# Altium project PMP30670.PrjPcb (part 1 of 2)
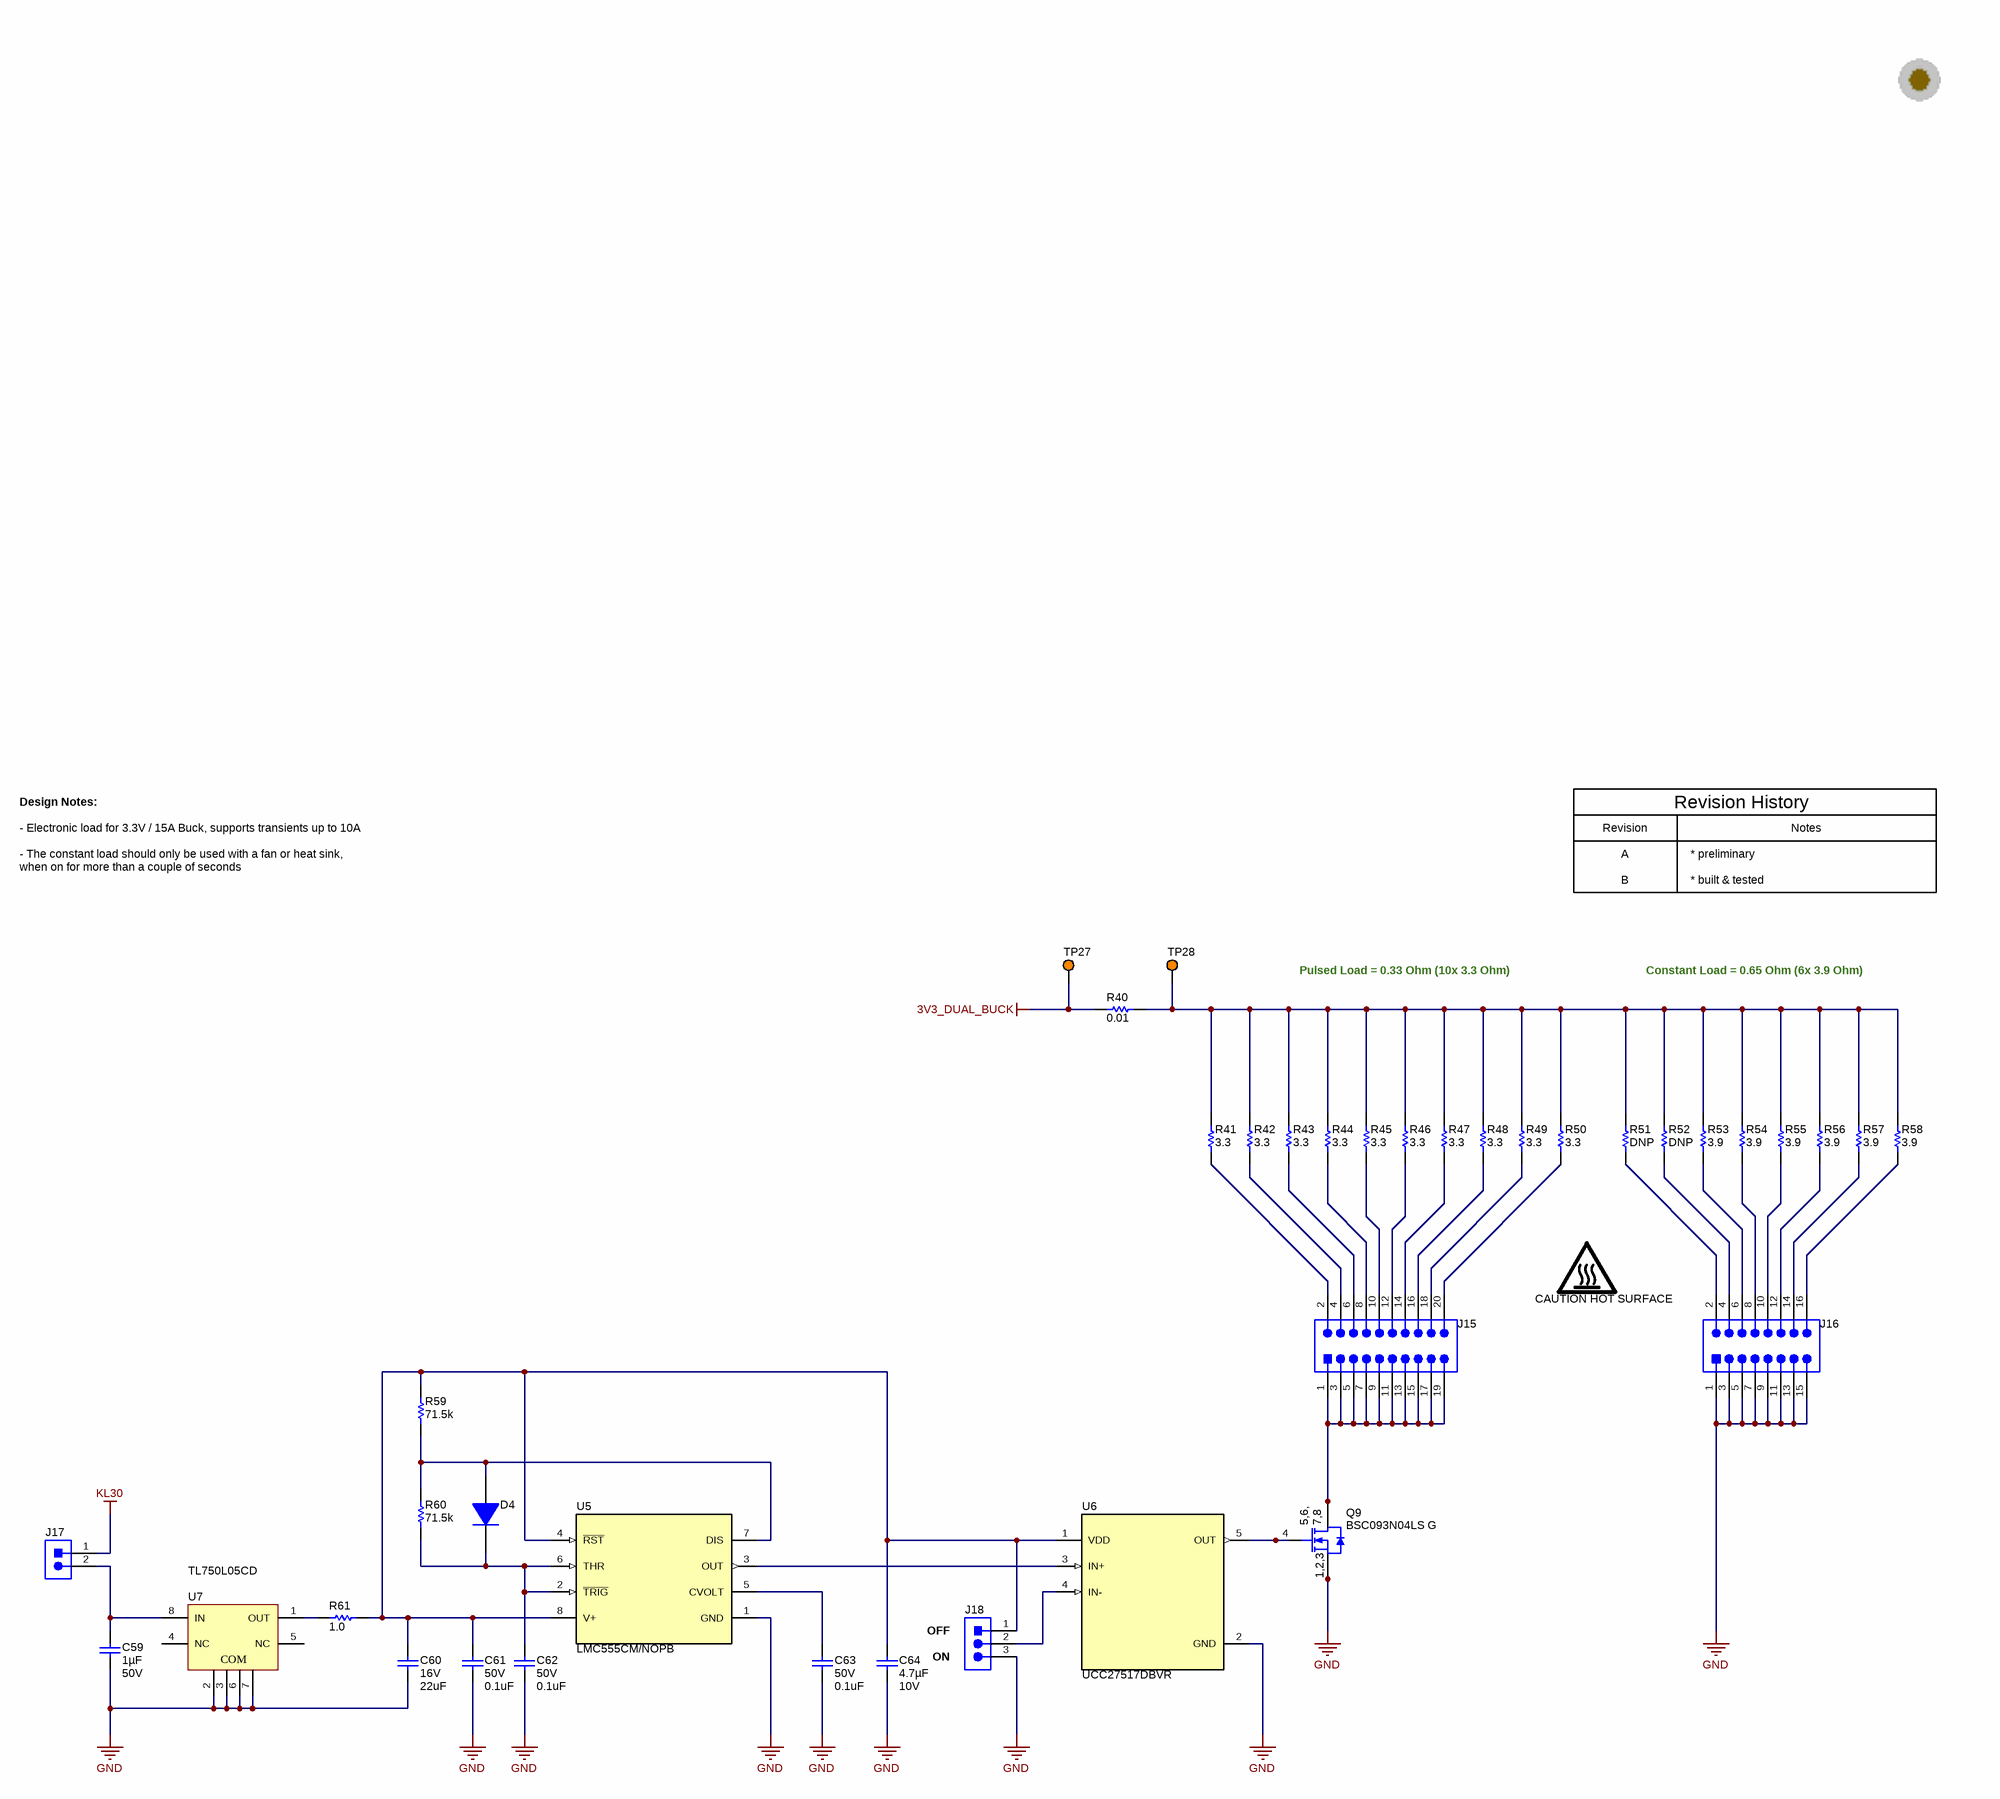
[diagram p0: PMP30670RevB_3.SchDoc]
TID: N/A; TechSupport: http://www.ti.com/support; SCH_Rev: B; PRJ_Title: Automotive Frontend Power Supply; PRJ_Number: PMP30670; PRJ_Engineer: M Zehendner; PRJ_Customer: Public Release; PCB_Rev: A; CopyrightYear: 2019
3 sheets, 200 parts. Net scope: global (net labels, ports and power ports of the same name join across sheets).
Board file: PMP30670.PcbDoc
Sheets:
  PMP30670RevB_3.SchDoc
  PMP30670RevB_2.SchDoc
  PMP30670RevB_1.SchDoc

## Sheet PMP30670RevB_3.SchDoc: PMP30670RevA_3
size A3; Date: Not shown in title block; ApprovedBy: Not shown in title block; CheckedBy: Not shown in title block; Author: Not shown in title block; CompanyName: Not shown in title block; DrawnBy: M Zehendner; Engineer: Not shown in title block; Organization: Not shown in title block; Address1: Not shown in title block; Address2: Not shown in title block; Address3: Not shown in title block; Address4: Not shown in title block; DocumentNumber: 3; Revision: Use project parameter SCH_Rev; SheetNumber: 3; SheetTotal: 3; PageSetup: Record=PageOptions¦CenterHorizontal=True¦CenterVertical=True¦PrintScale=0.70¦XCorrection=1.00¦YCorrection=1.00¦PrintKind=0¦BorderSize=5000000¦LeftOffset=0¦BottomOffset=0¦Orientation=2¦PaperLength=1000¦PaperWidth=1000¦Scale=100¦PaperSource=15¦PrintQuality=600¦MediaType=1¦DitherType=10¦PaperKind=A4¦PrintScaleMode=1

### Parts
C59  Cap_F: 1µF  VDC_V: 50V  [0805_HV]  (hidden comment: GRM21BR71H105KA12L)
C60  VDC_V: 16V  ValueDisplayed: 22uF  [1210_270]  (hidden comment: GRM32ER71C226ME18L)
C61  VDC_V: 50V  ValueDisplayed: 0.1uF  [0402]  (hidden comment: GRM155R71H104ME14D)
C62  VDC_V: 50V  ValueDisplayed: 0.1uF  [0402]  (hidden comment: GRM155R71H104ME14D)
C63  VDC_V: 50V  ValueDisplayed: 0.1uF  [0402]  (hidden comment: GRM155R71H104ME14D)
C64  Cap_F: 4.7µF  VDC_V: 10V  [0805_HV]  (hidden comment: GRM21BR71A475KA73L)
CAUTION!_HOT_SURFACE!1  CAUTION HOT SURFACE  [IEC_HotSurface_Large]  (no BOM)
D4  1N4148WFL-G3-08  [SOD-123FL]  (value not drawn)
J15  TSW-110-07-G-D  [TSW-110-07-G-D]  (value not drawn)
J16  TSW-108-07-G-D  [TSW-108-07-G-D]  (value not drawn)
J17  TSW-102-07-G-S  [TSW-102-07-G-S]  (value not drawn)
J18  TSW-103-07-G-S  [TSW-103-07-G-S]  (value not drawn)
Q9  BSC093N04LS G  [PG-TDSON-8]
R40  ValueDisplayed: 0.01  [PWR4412-2S-3W]  (hidden comment: OAR3R010FLF)
R41  ValueDisplayed: 3.3  [2512]  (hidden comment: CRCW25123R30JNEG)
R42  ValueDisplayed: 3.3  [2512]  (hidden comment: CRCW25123R30JNEG)
R43  ValueDisplayed: 3.3  [2512]  (hidden comment: CRCW25123R30JNEG)
R44  ValueDisplayed: 3.3  [2512]  (hidden comment: CRCW25123R30JNEG)
R45  ValueDisplayed: 3.3  [2512]  (hidden comment: CRCW25123R30JNEG)
R46  ValueDisplayed: 3.3  [2512]  (hidden comment: CRCW25123R30JNEG)
R47  ValueDisplayed: 3.3  [2512]  (hidden comment: CRCW25123R30JNEG)
R48  ValueDisplayed: 3.3  [2512]  (hidden comment: CRCW25123R30JNEG)
R49  ValueDisplayed: 3.3  [2512]  (hidden comment: CRCW25123R30JNEG)
R50  ValueDisplayed: 3.3  [2512]  (hidden comment: CRCW25123R30JNEG)
R51  ValueDisplayed: DNP  [2512]  (hidden comment: CRCW251212R1FKEG)
R52  ValueDisplayed: DNP  [2512]  (hidden comment: CRCW251212R1FKEG)
R53  ValueDisplayed: 3.9  [2512]  (hidden comment: CRCW25123R90JNEG)
R54  ValueDisplayed: 3.9  [2512]  (hidden comment: CRCW25123R90JNEG)
R55  ValueDisplayed: 3.9  [2512]  (hidden comment: CRCW25123R90JNEG)
R56  ValueDisplayed: 3.9  [2512]  (hidden comment: CRCW25123R90JNEG)
R57  ValueDisplayed: 3.9  [2512]  (hidden comment: CRCW25123R90JNEG)
R58  ValueDisplayed: 3.9  [2512]  (hidden comment: CRCW25123R90JNEG)
R59  ValueDisplayed: 71.5k  [0603]  (hidden comment: CRCW060371K5FKEA)
R60  ValueDisplayed: 71.5k  [0603]  (hidden comment: CRCW060371K5FKEA)
R61  ValueDisplayed: 1.0  [0603]  (hidden comment: CRCW06031R00JNEA)
TP27  5013  [Keystone5013]  (value not drawn)
TP28  5013  [Keystone5013]  (value not drawn)
U5  LMC555CM/NOPB  [D0008A_N]
U6  UCC27517DBVR  [DBV0005A_N]
U7  TL750L05CD  [D0008A_N]

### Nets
3V3_DUAL_BUCK: R40.1 TP27.1
GND: C59.2 C60.2 C61.2 C62.2 C63.2 C64.2 J16.1 J16.3 J16.5 J16.7 J16.9 J16.11 J16.13 J16.15 J18.3 Q9.1(S) Q9.2(S) Q9.3(S) U5.1(GND) U6.2(GND) U7.2(COM) U7.3(COM) U7.6(COM) U7.7(COM)
KL30: J17.1
NetC59_1: C59.1 J17.2 U7.8(IN)
NetC60_1: C60.1 C61.1 C64.1 J18.1 R59.2 R61.2 U5.4(~{RST}) U5.8(V+) U6.1(VDD)
NetC62_1: C62.1 D4.1(K) R60.1 U5.2(~{TRIG}) U5.6(THR)
NetC63_1: C63.1 U5.5(CVOLT)
NetD4_2: D4.2(A) R59.1 R60.2 U5.7(DIS)
NetJ15_1: J15.1 J15.3 J15.5 J15.7 J15.9 J15.11 J15.13 J15.15 J15.17 J15.19 Q9.5(D) Q9.6(D) Q9.7(D) Q9.8(D) Q9.9(D)
NetJ15_2: J15.2 R41.1
NetJ15_4: J15.4 R42.1
NetJ15_6: J15.6 R43.1
NetJ15_8: J15.8 R44.1
NetJ15_10: J15.10 R45.1
NetJ15_12: J15.12 R46.1
NetJ15_14: J15.14 R47.1
NetJ15_16: J15.16 R48.1
NetJ15_18: J15.18 R49.1
NetJ15_20: J15.20 R50.1
NetJ16_2: J16.2 R51.1
NetJ16_4: J16.4 R52.1
NetJ16_6: J16.6 R53.1
NetJ16_8: J16.8 R54.1
NetJ16_10: J16.10 R55.1
NetJ16_12: J16.12 R56.1
NetJ16_14: J16.14 R57.1
NetJ16_16: J16.16 R58.1
NetJ18_2: J18.2 U6.4(IN-)
NetQ9_4: Q9.4(G) U6.5(OUT)
NetR40_2: R40.2 R41.2 R42.2 R43.2 R44.2 R45.2 R46.2 R47.2 R48.2 R49.2 R50.2 R51.2 R52.2 R53.2 R54.2 R55.2 R56.2 R57.2 R58.2 TP28.1
NetR61_1: R61.1 U7.1(OUT)
NetU5_3: U5.3(OUT) U6.3(IN+)

Not connected (* = marked no-connect by the designer): U7 4(NC) 5(NC)

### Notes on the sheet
- Design Notes:
- - Electronic load for 3.3V / 15A Buck, supports transients up to 10A
- - The constant load should only be used with a fan or heat sink,
- Revision
- A
- * preliminary
- Revision History
- Notes
- when on for more than a couple of seconds
- B
- * built & tested
- Pulsed Load = 0.33 Ohm (10x 3.3 Ohm)
- Constant Load = 0.65 Ohm (6x 3.9 Ohm)
- OFF
- ON

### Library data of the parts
C59 = CMP-0008350-2: CAP, CERM, 1 uF, 50 V, +/- 10%, X7R, 0805; Manufacturer: MuRata; TaMin_C: -55°C; Polarized: N; SizeAreaWB_mm2: 6.75; Value1: Unknown; U/M: EA; Value: 1uF; TaMax_C: 125°C; SizeZ_mm: 1.45; SizeX_mm: 2; SizeY_mm: 1.25; Cap_Case: 0805; SizeArea_mm2: 2.5; AEC Category: Q200
C60 = CMP-0009223-2: CAP, CERM, 22 uF, 16 V, +/- 20%, X7R, 1210; Manufacturer: MuRata; TaMin_C: -55°C; ESR_ohm: 3m; Polarized: N; SizeAreaWB_mm2: 14.7; Value1: 0.003 ohm; U/M: EA; Value: 22uF; TaMax_C: 125°C; SizeZ_mm: 2.7; SizeX_mm: 3.2; SizeY_mm: 2.5; Cap_Case: 1210; SizeArea_mm2: 8; Cap_F: 22µF; IRMS_A: 3.2A; AEC Category: Q200
C61-C63 = CMP-0006675-2: CAP, CERM, 0.1 uF, 50 V, +/- 20%, X7R, 0402; Manufacturer: MuRata; TaMin_C: -55°C; Polarized: N; SizeAreaWB_mm2: 3; Value1: Unknown; U/M: EA; Value: 0.1uF; TaMax_C: 125°C; SizeZ_mm: 0.6; SizeX_mm: 1; SizeY_mm: 0.5; Cap_F: 100nF; AEC Category: Q200
C64 = CMP-0008320-2: CAP, CERM, 4.7 uF, 10 V, +/- 10%, X7R, 0805; Manufacturer: MuRata; TaMin_C: -55°C; Polarized: N; SizeAreaWB_mm2: 6.75; Value1: Unknown; U/M: EA; Value: 4.7uF; TaMax_C: 125°C; SizeZ_mm: 1.45; SizeX_mm: 2; SizeY_mm: 1.25; Cap_Case: 0805; SizeArea_mm2: 2.5; AEC Category: Q200
CAUTION!_HOT_SURFACE!1 = CMP-0074837-1: IEC 61010-1 Hot Surface Warning; SymbolCreator: a0412235
D4 = CMP-0076920-2: Diode, Switching, 100 V, 0.15 A, SOD-123FL; Manufacturer: Vishay-Semiconductor; Vr_V: 100V; Green_Lifecycle: Not Set; SizeY_mm: 1.65; SizeAreaWB_mm2: 12.19; Io_A: 150mA; SizeZ_mm: 0.98; Green_REACh: Incomplete; Value1: 0.15A; Vf_V: 1.2V; SizeArea_mm2: 5.94; SizeX_mm: 3.6; Value: 100V; TJmax_C: 150°C; AEC Category: Q101
J15 = CMP-0075421-2: Header, 100mil, 10x2, Gold, TH; Manufacturer: Samtec; Pitch_mm: 2.54; Cert_VDE: N; Gender: Male; Cert_CSA: Y; Voltage_V: 550V; Green_REACh: Passed; Current_A: 6.3A; Green_Lifecycle: Active; Row_Count: 2
J16 = CMP-0075418-1: Header, 100mil, 8x2, Gold, TH; Manufacturer: Samtec; Pitch_mm: 2.54; Cert_VDE: N; Gender: Male; Cert_CSA: Y; Voltage_V: 550V; Green_REACh: Passed; Current_A: 6.3A; CT: False; Green_Lifecycle: Active; Row_Count: 2; CNHeader: True
J17 = CMP-0075405-2: Header, 100mil, 2x1, Gold, TH; Manufacturer: Samtec; Pitch_mm: 2.54; Cert_VDE: N; Gender: Male; Cert_CSA: Y; Voltage_V: 550V; Green_REACh: Passed; Current_A: 6.3A; Green_Lifecycle: Active; Row_Count: 1
J18 = CMP-0075407-2: Header, 100mil, 3x1, Gold, TH; Manufacturer: Samtec; Pitch_mm: 2.54; Cert_VDE: N; Gender: Male; Cert_CSA: Y; Voltage_V: 550V; Green_REACh: Passed; Current_A: 6.3A; Green_Lifecycle: Active; Row_Count: 1
Q9 = CMP-0000690-1: MOSFET, N-CH, 40 V, 49 A, PG-TDSON-8; Alternate Manufacturer: None; Manufacturer: Infineon Technologies; SizeZ_mm: 1.12; ChType: N; Value2: 18 nC; Value1: 0.013; VdsMax_V: 40V; SizeX_mm: 5.99; SizeY_mm: 4.9; Vgs_V: 20V; Value: 40V; Rdson45_ohm: 0.0137; SizeArea_mm2: 29.351; AEC Category: Q101; IdsMax_A: 49A; SizeAreaWB_mm2: 55.131; U/M: EA; QgTyp_nC: 18
R40 = CMP-0014307-3: RES, 0.01, 1%, 3 W, 15.2x1.0x25.4; Manufacturer: TT Electronics/IRC; Power_W: 3W; TempCo: 20 ppm/C; Value_Code: R010; U/M: EA; Value: 0.01; EIA_Code: E96; AEC Category: Q200
R41-R50 = CMP-0015960-1: RES, 3.3, 5%, 1 W, AEC-Q200 Grade 0, 2512; Manufacturer: Vishay-Dale; Power_W: 1W; TempCo: 200 ppm/C; Value_Code: 3R30; U/M: EA; Value: 3.3; EIA_Code: E24; SizeX_mm: 6.3; SizeY_mm: 3.2; SizeZ_mm: 0.71; SizeArea_mm2: 20.16; AEC Qualified: Y; VDC_V: 500V; AEC Grade: 0; AEC Category: Q200
R51 R52 = CMP-0015453-3: RES, 12.1, 1%, 1 W, AEC-Q200 Grade 0, 2512; Manufacturer: Vishay-Dale; Power_W: 1W; TempCo: 100 ppm/C; Value_Code: 12R1; Value: 12.1; EIA_Code: E96; SizeX_mm: 6.3; SizeY_mm: 3.2; SizeZ_mm: 0.71; SizeArea_mm2: 20.16; AEC Qualified: Y; VDC_V: 500V; AEC Grade: 0; AEC Category: Q200
R53-R58 = CMP-0015962-1: RES, 3.9, 5%, 1 W, AEC-Q200 Grade 0, 2512; Manufacturer: Vishay-Dale; Power_W: 1W; TempCo: 200 ppm/C; Value_Code: 3R90; U/M: EA; Value: 3.9; EIA_Code: E24; SizeX_mm: 6.3; SizeY_mm: 3.2; SizeZ_mm: 0.71; SizeArea_mm2: 20.16; AEC Qualified: Y; VDC_V: 500V; AEC Grade: 0; AEC Category: Q200
R59 R60 = CMP-0022581-4: RES, 71.5 k, 1%, 0.1 W, AEC-Q200 Grade 0, 0603; Manufacturer: Vishay-Dale; Power_W: 100mW; TempCo: 100 ppm/C; Value_Code: 71k5; Value: 71.5k; EIA_Code: E96; SizeX_mm: 1.6; SizeY_mm: 0.8; SizeZ_mm: 1; Value2: 0.1W; SizeArea_mm2: 1.28; AEC Qualified: Y; VDC_V: 75V; AEC Category: Q200; AEC Grade: 0
R61 = CMP-0025743-1: RES, 1.0, 5%, 0.1 W, 0603; Manufacturer: Vishay-Dale; Power_W: 100mW; TempCo: 200 ppm/C; Value_Code: 1R00; U/M: EA; Value: 1.0; EIA_Code: E24; Res_ohm: 1; SizeX_mm: 1.6; SizeY_mm: 0.8; Value2: 0.1W; SizeArea_mm2: 1.28; VDC_V: 75V; AEC Category: Q200
TP27 TP28 = CMP-0055150-1: Test Point, Multipurpose, Orange, TH; Manufacturer: Keystone; CNHeader: FALSE; Green_Lifecycle: Active; Green_REACh: Passed; ContactFinish: Silver; CT: TRUE
U5 = CMP-0068883-1: CMOS Timer, 8-pin Narrow SOIC, Pb-Free; Manufacturer: Texas Instruments; PackageTopMarking: NSZXTT*LMC*555CM; PowerWise: N; CompType: Analog IC
U6 = CMP-0066947-1: 4A/4A Single Channel High-speed Low-side Gate Driver, DBV0005A (SOT-23-5); Alternate PartNumber: UCC27517DBVT; Alternate Manufacturer: Texas Instruments; Green_Lifecycle: Active; SizeAreaWB_mm2: 14.82; Green_REACh: Passed; U/M: EA; SizeZ_mm: 1.45; SizeX_mm: 2.8; SizeY_mm: 2.9; SizeArea_mm2: 8.12; CompType: IC
U7 = CMP-0035296-1: Single Output LDO, 150 mA, Fixed 5 V Output, 6 to 26 V Input, with Low IQ, 8-pin SOIC (D), 0 to 125 degC, Green (RoHS & no Sb/Br); Manufacturer: Texas Instruments; Vin(Min)(V): 6; Vout Adj(Min)(V): 5; Vin(Max)(V): 26; Iout(Max)(A): 0.15; Iq(Typ)(mA): 1; Vdo(Typ)(mV): 600; Rating: Catalog; SubFamily: Single Channel LDO; Accuracy(%): 4

## Sheet PMP30670RevB_2.SchDoc: PMP30670RevA_2
size A3; Date: Not shown in title block; ApprovedBy: Not shown in title block; CheckedBy: Not shown in title block; Author: Not shown in title block; CompanyName: Not shown in title block; DrawnBy: M Zehendner; Engineer: Not shown in title block; Organization: Not shown in title block; Address1: Not shown in title block; Address2: Not shown in title block; Address3: Not shown in title block; Address4: Not shown in title block; DocumentNumber: 2; Revision: Use project parameter SCH_Rev; SheetNumber: 2; SheetTotal: 3; PageSetup: Record=PageOptions¦CenterHorizontal=True¦CenterVertical=True¦PrintScale=0.70¦XCorrection=1.00¦YCorrection=1.00¦PrintKind=0¦BorderSize=5000000¦LeftOffset=0¦BottomOffset=0¦Orientation=2¦PaperLength=1000¦PaperWidth=1000¦Scale=100¦PaperSource=15¦PrintQuality=600¦MediaType=1¦DitherType=10¦PaperKind=A4¦PrintScaleMode=1
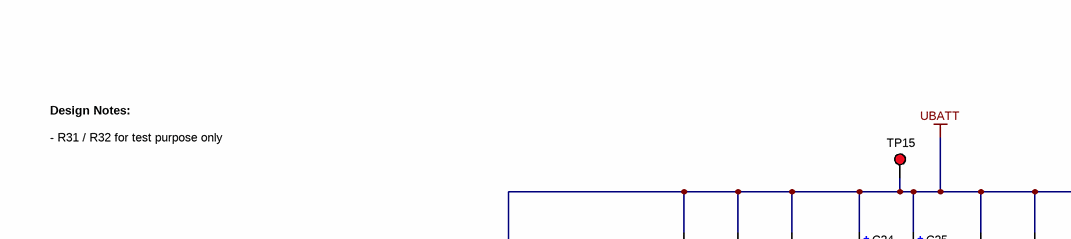
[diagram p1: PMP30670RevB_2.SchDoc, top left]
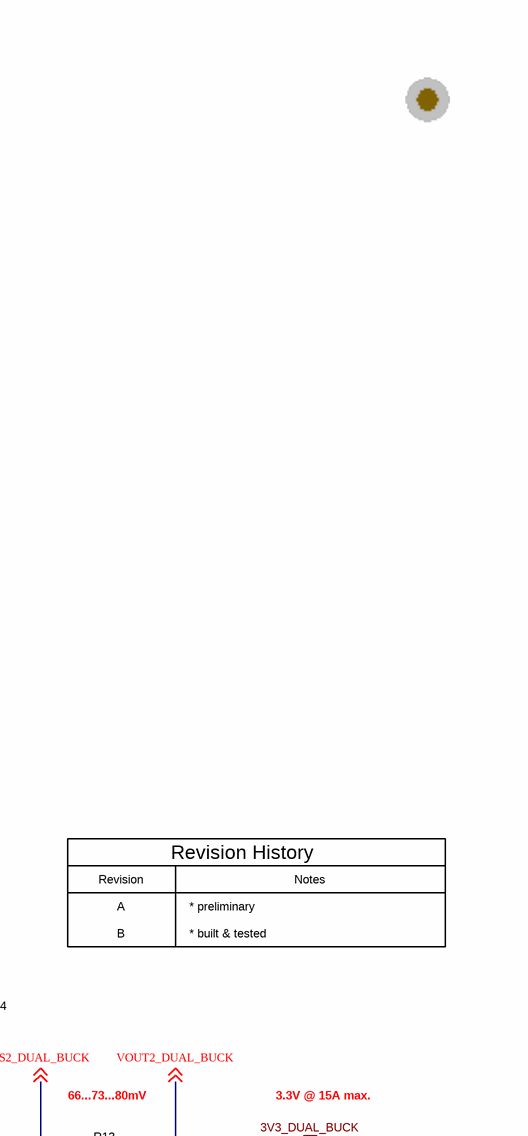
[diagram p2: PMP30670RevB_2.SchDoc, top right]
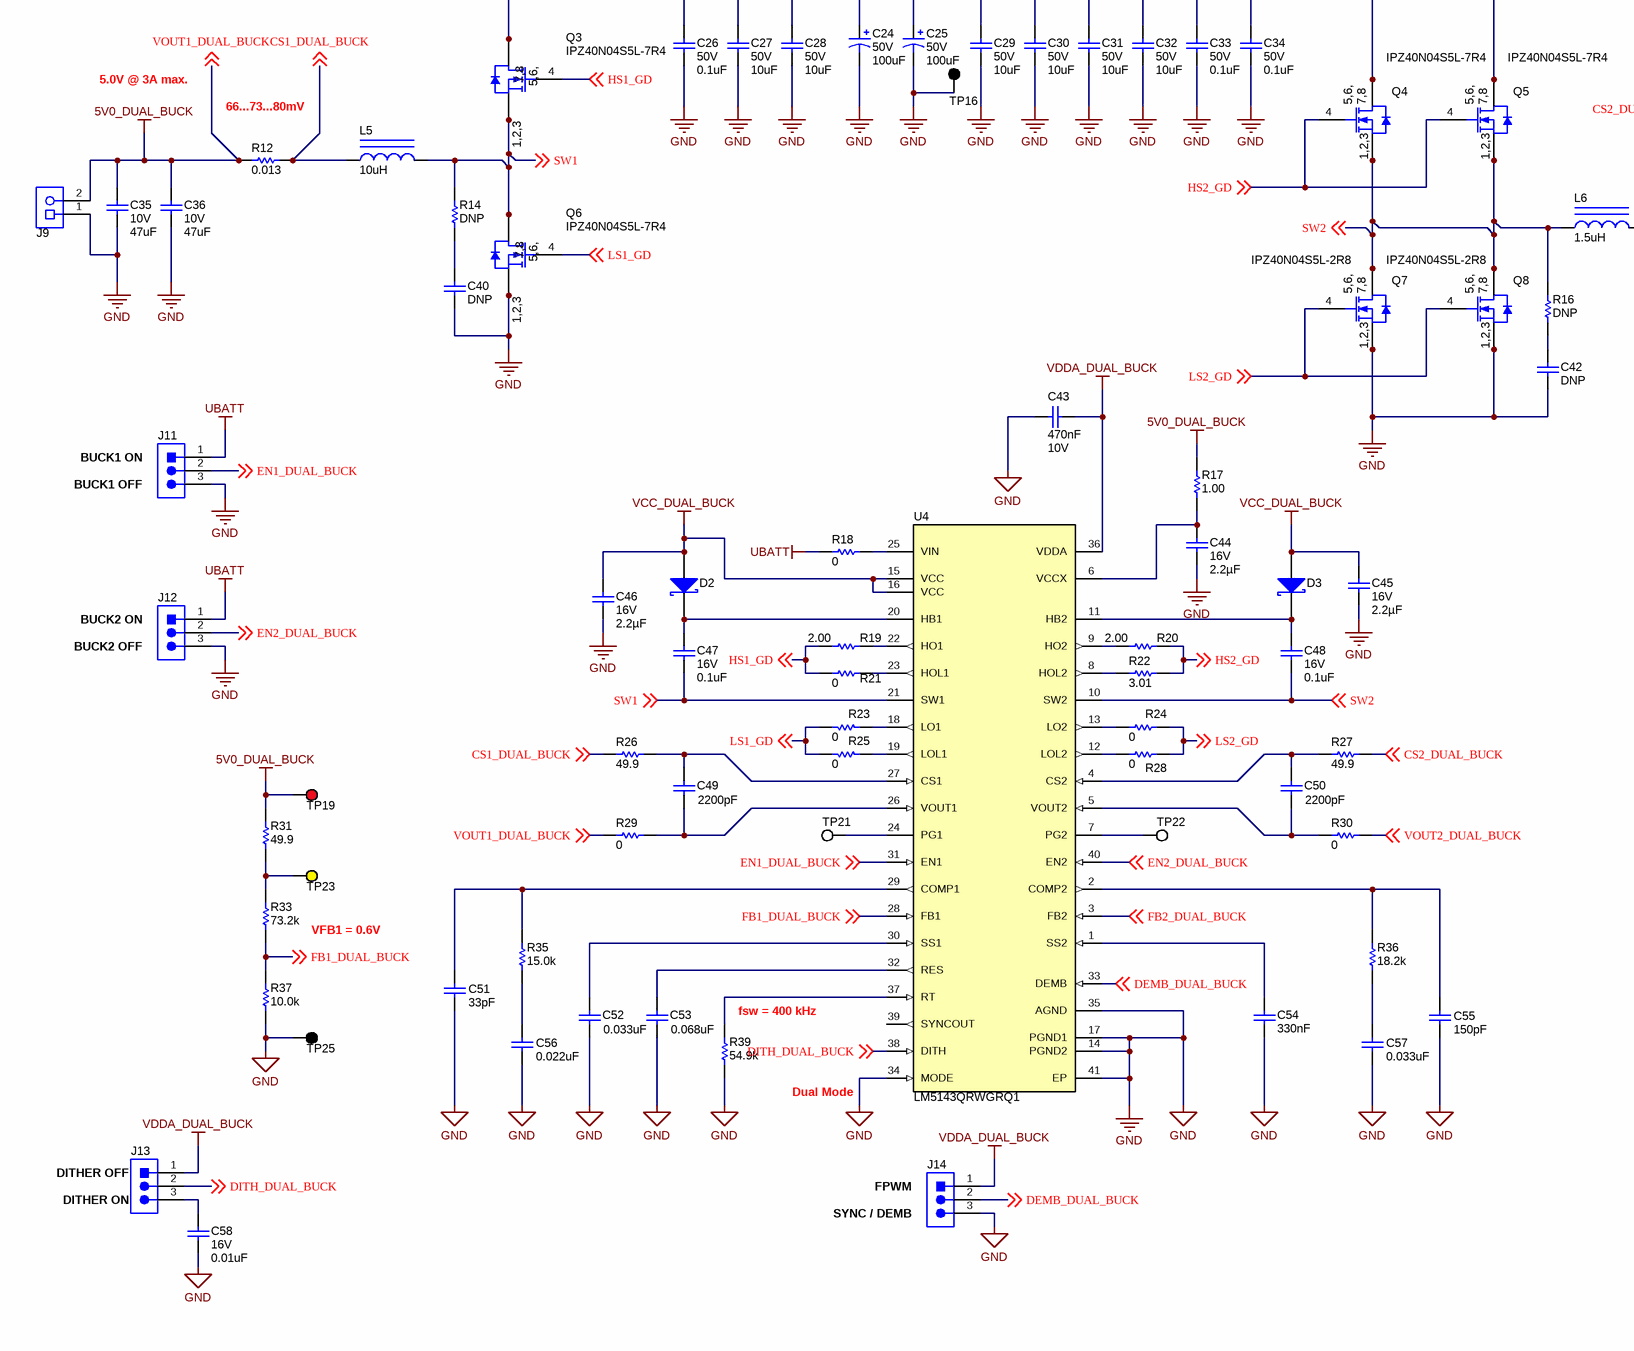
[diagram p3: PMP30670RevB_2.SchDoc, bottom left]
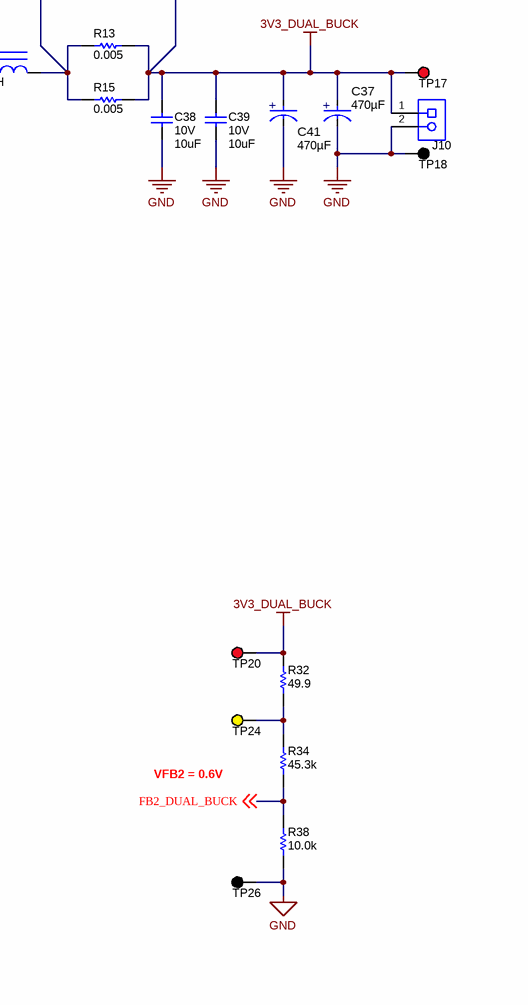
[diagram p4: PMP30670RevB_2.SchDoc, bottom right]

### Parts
C24  VDC_V: 50V  ValueDisplayed: 100uF  [Panasonic_G]  (hidden comment: EEH-ZC1H101P)
C25  VDC_V: 50V  ValueDisplayed: 100uF  [Panasonic_G]  (hidden comment: EEH-ZC1H101P)
C26  VDC_V: 50V  ValueDisplayed: 0.1uF  [0402]  (hidden comment: GRM155R71H104ME14D)
C27  VDC_V: 50V  ValueDisplayed: 10uF  [1210_270]  (hidden comment: GRM32ER71H106KA12L)
C28  VDC_V: 50V  ValueDisplayed: 10uF  [1210_270]  (hidden comment: GRM32ER71H106KA12L)
C29  VDC_V: 50V  ValueDisplayed: 10uF  [1210_270]  (hidden comment: GRM32ER71H106KA12L)
C30  VDC_V: 50V  ValueDisplayed: 10uF  [1210_270]  (hidden comment: GRM32ER71H106KA12L)
C31  VDC_V: 50V  ValueDisplayed: 10uF  [1210_270]  (hidden comment: GRM32ER71H106KA12L)
C32  VDC_V: 50V  ValueDisplayed: 10uF  [1210_270]  (hidden comment: GRM32ER71H106KA12L)
C33  VDC_V: 50V  ValueDisplayed: 0.1uF  [0402]  (hidden comment: GRM155R71H104ME14D)
C34  VDC_V: 50V  ValueDisplayed: 0.1uF  [0402]  (hidden comment: GRM155R71H104ME14D)
C35  VDC_V: 10V  ValueDisplayed: 47uF  [1210_270]  (hidden comment: GRM32ER71A476ME15L)
C36  VDC_V: 10V  ValueDisplayed: 47uF  [1210_270]  (hidden comment: GRM32ER71A476ME15L)
C37  Cap_F: 470µF  [FP-HHXB160ARA471MJA0G_RADIAL-MFG]  (hidden comment: HHXB160ARA471MJA0G)
C38  VDC_V: 10V  ValueDisplayed: 10uF  [1210_220]  (hidden comment: GRM32DR71A106MA01L)
C39  VDC_V: 10V  ValueDisplayed: 10uF  [1210_220]  (hidden comment: GRM32DR71A106MA01L)
C40  Cap_F: DNP  [0805_HV]  (hidden comment: GRM21AR72E222KW01D)
C41  Cap_F: 470µF  [FP-HHXB160ARA471MJA0G_RADIAL-MFG]  (hidden comment: HHXB160ARA471MJA0G)
C42  Cap_F: DNP  [0805_HV]  (hidden comment: GRM21AR72E222KW01D)
C43  Cap_F: 470nF  VDC_V: 10V  [0603]  (hidden comment: GRM188R71A474KA61D)
C44  VDC_V: 16V  Cap_F: 2.2µF  [0603]  (hidden comment: GRM188Z71C225KE43)
C45  VDC_V: 16V  Cap_F: 2.2µF  [0603]  (hidden comment: GRM188Z71C225KE43)
C46  VDC_V: 16V  Cap_F: 2.2µF  [0603]  (hidden comment: GRM188Z71C225KE43)
C47  VDC_V: 16V  ValueDisplayed: 0.1uF  [0402]  (hidden comment: GRM155R71C104KA88D)
C48  VDC_V: 16V  ValueDisplayed: 0.1uF  [0402]  (hidden comment: GRM155R71C104KA88D)
C49  ValueDisplayed: 2200pF  [0402]  (hidden comment: GRM155R72A222KA01D)
C50  ValueDisplayed: 2200pF  [0402]  (hidden comment: GRM155R72A222KA01D)
C51  ValueDisplayed: 33pF  [0402]  (hidden comment: GRM1555C1H330JA01D)
C52  ValueDisplayed: 0.033uF  [0402]  (hidden comment: GRM155R71A333KA01D)
C53  ValueDisplayed: 0.068uF  [0402]  (hidden comment: GRM155R71A683KA01D)
C54  Cap_F: 330nF  [0603]  (hidden comment: GRM188R71A334KA61D)
C55  ValueDisplayed: 150pF  [0402]  (hidden comment: GRM1555C1H151JA01D)
C56  ValueDisplayed: 0.022uF  [0402]  (hidden comment: GRM155R71C223KA01D)
C57  ValueDisplayed: 0.033uF  [0402]  (hidden comment: GRM155R71C333KA01D)
C58  VDC_V: 16V  ValueDisplayed: 0.01uF  [0402]  (hidden comment: GRM155R71C103KA01D)
D2  PMEG6010CEH,115  [SOD-123F]  (value not drawn)
D3  PMEG6010CEH,115  [SOD-123F]  (value not drawn)
J9  691 101 710 002  [Wurth_691101710002]  (value not drawn)
J10  691 101 710 002  [Wurth_691101710002]  (value not drawn)
J11  800-10-003-10-001000  [Mill-Max_800-10-003-10-001000]  (value not drawn)
J12  800-10-003-10-001000  [Mill-Max_800-10-003-10-001000]  (value not drawn)
J13  800-10-003-10-001000  [Mill-Max_800-10-003-10-001000]  (value not drawn)
J14  800-10-003-10-001000  [Mill-Max_800-10-003-10-001000]  (value not drawn)
L5  ValueDisplayed: 10uH  [XAL6060]  (hidden comment: XAL6060-103MEB)
L6  ValueDisplayed: 1.5uH  [XAL1010]  (hidden comment: XAL1010-152MEB)
Q3  IPZ40N04S5L-7R4  [PG-TSDSON-8-32]
Q4  IPZ40N04S5L-7R4  [PG-TSDSON-8-32]
Q5  IPZ40N04S5L-7R4  [PG-TSDSON-8-32]
Q6  IPZ40N04S5L-7R4  [PG-TSDSON-8-32]
Q7  IPZ40N04S5L-2R8  [PG-TSDSON-8-32]
Q8  IPZ40N04S5L-2R8  [PG-TSDSON-8-32]
R12  ValueDisplayed: 0.013  [0612]  (hidden comment: PRL1632-R013-F-T1)
R13  ValueDisplayed: 0.005  [2010]  (hidden comment: CSNL2010FT5L00)
R14  ValueDisplayed: DNP  [0805_HV]  (hidden comment: CRCW08051R00JNEA)
R15  ValueDisplayed: 0.005  [2010]  (hidden comment: CSNL2010FT5L00)
R16  ValueDisplayed: DNP  [1206]  (hidden comment: CRCW12061R00FKEA)
R17  ValueDisplayed: 1.00  [0603]  (hidden comment: CRCW06031R00FKEA)
R18  ValueDisplayed: 0  [0603]  (hidden comment: ERJ-3GEY0R00V)
R19  ValueDisplayed: 2.00  [0603]  (hidden comment: CRCW06032R00FKEA)
R20  ValueDisplayed: 2.00  [0603]  (hidden comment: CRCW06032R00FKEA)
R21  ValueDisplayed: 0  [0603]  (hidden comment: ERJ-3GEY0R00V)
R22  ValueDisplayed: 3.01  [0603]  (hidden comment: CRCW06033R01FKEA)
R23  ValueDisplayed: 0  [0603]  (hidden comment: ERJ-3GEY0R00V)
R24  ValueDisplayed: 0  [0603]  (hidden comment: ERJ-3GEY0R00V)
R25  ValueDisplayed: 0  [0603]  (hidden comment: ERJ-3GEY0R00V)
R26  ValueDisplayed: 49.9  [0603]  (hidden comment: CRCW060349R9FKEA)
R27  ValueDisplayed: 49.9  [0603]  (hidden comment: CRCW060349R9FKEA)
R28  ValueDisplayed: 0  [0603]  (hidden comment: ERJ-3GEY0R00V)
R29  ValueDisplayed: 0  [0603]  (hidden comment: ERJ-3GEY0R00V)
R30  ValueDisplayed: 0  [0603]  (hidden comment: ERJ-3GEY0R00V)
R31  ValueDisplayed: 49.9  [0603]  (hidden comment: CRCW060349R9FKEA)
R32  ValueDisplayed: 49.9  [0603]  (hidden comment: CRCW060349R9FKEA)
R33  ValueDisplayed: 73.2k  [0603]  (hidden comment: CRCW060373K2FKEA)
R34  ValueDisplayed: 45.3k  [0603]  (hidden comment: CRCW060345K3FKEA)
R35  ValueDisplayed: 15.0k  [0603]  (hidden comment: CRCW060315K0FKEA)
R36  ValueDisplayed: 18.2k  [0603]  (hidden comment: CRCW060318K2FKEA)
R37  ValueDisplayed: 10.0k  [0603]  (hidden comment: CRCW060310K0FKEA)
R38  ValueDisplayed: 10.0k  [0603]  (hidden comment: CRCW060310K0FKEA)
R39  ValueDisplayed: 54.9k  [0603]  (hidden comment: CRCW060354K9FKEA)
TP15  5010  [Keystone5010]  (value not drawn)
TP16  5011  [Keystone5011]  (value not drawn)
TP17  5010  [Keystone5010]  (value not drawn)
TP18  5011  [Keystone5011]  (value not drawn)
TP19  5010  [Keystone5010]  (value not drawn)
TP20  5010  [Keystone5010]  (value not drawn)
TP21  5012  [Keystone5012]  (value not drawn)
TP22  5012  [Keystone5012]  (value not drawn)
TP23  5014  [Keystone5014]  (value not drawn)
TP24  5014  [Keystone5014]  (value not drawn)
TP25  5011  [Keystone5011]  (value not drawn)
TP26  5011  [Keystone5011]  (value not drawn)
U4  LM5143QRWGRQ1  [RWG0040A]

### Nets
3V3_DUAL_BUCK: C37.2(ANODE) C38.1 C39.1 C41.2(ANODE) J10.1 R13.2 R15.2 R30.2 R32.2 TP17.1 TP20.1 ; off-sheet VOUT2_DUAL_BUCK  [also labelled VOUT2_DUAL_BUCK]
5V0_DUAL_BUCK: C35.1 C36.1 J9.2 R12.1 R17.2 R29.1 R31.2 TP19.1 ; off-sheet VOUT1_DUAL_BUCK  [also labelled VOUT1_DUAL_BUCK]
GND: C24.2(-) C25.2(-) C26.2 C27.2 C28.2 C29.2 C30.2 C31.2 C32.2 C33.2 C34.2 C35.2 C36.2 C37.1(CATHODE) C38.2 C39.2 C40.2 C41.1(CATHODE) C42.2 C43.1 C44.2 C45.2 C46.2 C51.2 C52.2 C53.2 C54.2 C55.2 C56.2 C57.2 C58.2 J9.1 J10.2 J11.3 J12.3 J14.3 Q6.1(S) Q6.2(S) Q6.3(S) Q7.1(S) Q7.2(S) Q7.3(S) Q8.1(S) Q8.2(S) Q8.3(S) R37.1 R38.1 R39.1 TP16.1 TP18.1 TP25.1 TP26.1 U4.14(PGND2) U4.17(PGND1) U4.34(MODE) U4.35(AGND) U4.41(EP)
UBATT: C24.1(+) C25.1(+) C26.1 C27.1 C28.1 C29.1 C30.1 C31.1 C32.1 C33.1 C34.1 J11.1 J12.1 Q3.5(D) Q3.6(D) Q3.7(D) Q3.8(D) Q3.9(D) Q4.5(D) Q4.6(D) Q4.7(D) Q4.8(D) Q4.9(D) Q5.5(D) Q5.6(D) Q5.7(D) Q5.8(D) Q5.9(D) R18.1 TP15.1
VCC_DUAL_BUCK: C45.1 C46.1 D2.2(A) D3.2(A) U4.15(VCC) U4.16(VCC)
VDDA_DUAL_BUCK: C43.2 J13.1 J14.1 U4.36(VDDA)
CS1_DUAL_BUCK: L5.1 R12.2 R26.2 ; off-sheet CS1_DUAL_BUCK
CS2_DUAL_BUCK: L6.2 R13.1 R15.1 R27.1 ; off-sheet CS2_DUAL_BUCK
DEMB_DUAL_BUCK: J14.2 U4.33(DEMB) ; off-sheet DEMB_DUAL_BUCK
DITH_DUAL_BUCK: J13.2 U4.38(DITH) ; off-sheet DITH_DUAL_BUCK
EN1_DUAL_BUCK: J11.2 U4.31(EN1) ; off-sheet EN1_DUAL_BUCK
EN2_DUAL_BUCK: J12.2 U4.40(EN2) ; off-sheet EN2_DUAL_BUCK
FB1_DUAL_BUCK: R33.1 R37.2 U4.28(FB1) ; off-sheet FB1_DUAL_BUCK
FB2_DUAL_BUCK: R34.1 R38.2 U4.3(FB2) ; off-sheet FB2_DUAL_BUCK
HS1_GD: Q3.4(G) R19.2 R21.1 ; off-sheet HS1_GD
HS2_GD: Q4.4(G) Q5.4(G) R20.1 R22.2 ; off-sheet HS2_GD
LS1_GD: Q6.4(G) R23.2 R25.2 ; off-sheet LS1_GD
LS2_GD: Q7.4(G) Q8.4(G) R24.2 R28.2 ; off-sheet LS2_GD
SW1: C47.2 L5.2 Q3.1(S) Q3.2(S) Q3.3(S) Q6.5(D) Q6.6(D) Q6.7(D) Q6.8(D) Q6.9(D) R14.2 U4.21(SW1) ; off-sheet SW1
SW2: C48.2 L6.1 Q4.1(S) Q4.2(S) Q4.3(S) Q5.1(S) Q5.2(S) Q5.3(S) Q7.5(D) Q7.6(D) Q7.7(D) Q7.8(D) Q7.9(D) Q8.5(D) Q8.6(D) Q8.7(D) Q8.8(D) Q8.9(D) R16.2 U4.10(SW2) ; off-sheet SW2
NetC40_1: C40.1 R14.1
NetC42_1: C42.1 R16.1
NetC44_1: C44.1 R17.1 U4.6(VCCX)
NetC47_1: C47.1 D2.1(K) U4.20(HB1)
NetC48_1: C48.1 D3.1(K) U4.11(HB2)
NetC49_1: C49.1 R26.1 U4.27(CS1)
NetC49_2: C49.2 R29.2 U4.26(VOUT1)
NetC50_1: C50.1 R27.2 U4.4(CS2)
NetC50_2: C50.2 R30.1 U4.5(VOUT2)
NetC51_1: C51.1 R35.2 U4.29(COMP1)
NetC52_1: C52.1 U4.30(SS1)
NetC53_1: C53.1 U4.32(RES)
NetC54_1: C54.1 U4.1(SS2)
NetC55_1: C55.1 R36.2 U4.2(COMP2)
NetC56_1: C56.1 R35.1
NetC57_1: C57.1 R36.1
NetC58_1: C58.1 J13.3
NetR18_2: R18.2 U4.25(VIN)
NetR19_1: R19.1 U4.22(HO1)
NetR20_2: R20.2 U4.9(HO2)
NetR21_2: R21.2 U4.23(HOL1)
NetR22_1: R22.1 U4.8(HOL2)
NetR23_1: R23.1 U4.18(LO1)
NetR24_1: R24.1 U4.13(LO2)
NetR25_1: R25.1 U4.19(LOL1)
NetR28_1: R28.1 U4.12(LOL2)
NetR31_1: R31.1 R33.2 TP23.1
NetR32_1: R32.1 R34.2 TP24.1
NetR39_2: R39.2 U4.37(RT)
NetTP21_1: TP21.1 U4.24(PG1)
NetTP22_1: TP22.1 U4.7(PG2)

Not connected (* = marked no-connect by the designer): U4 39(SYNCOUT)

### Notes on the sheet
- Design Notes:
- - R31 / R32 for test purpose only
- Revision
- A
- * preliminary
- Revision History
- Notes
- B
- * built & tested
- 5.0V @ 3A max.
- 66...73...80mV
- (near R13) 66...73...80mV
- 3.3V @ 15A max.
- (near J11) BUCK1 ON
- (near J11) BUCK1 OFF
- (near J12) BUCK2 ON
- (near J12) BUCK2 OFF
- VFB1 = 0.6V
- VFB2 = 0.6V
- (near R39) fsw = 400 kHz
- Dual Mode
- (near J13) DITHER OFF
- (near J13) DITHER ON
- (near J14) FPWM
- (near J14) SYNC / DEMB

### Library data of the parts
C24 C25 = CMP-0064994-1: CAP, Polymer Hybrid, 100 uF, 50 V,+/- 20%, 0.028 ohm, AEC-Q200 Grade 1, D10xL10.2mm SMD; Manufacturer: Panasonic; TaMin_C: -55°C; ESR_ohm: 0.028; Polarized: Y; SizeAreaWB_mm2: 151.29; U/M: EA; Value: 100uF; TaMax_C: 125°C; SizeZ_mm: 10.5; SizeX_mm: 10.3; Cap_Case: 10x10.2mm; SizeArea_mm2: 106.09; CompType: Capacitor; Cap_F: 100µF; IRMS_A: 1.6A; AEC Grade: 1; AEC Category: Q200
C26 C33 C34 = CMP-0006675-2: as C61 on sheet PMP30670RevB_3
C27-C32 = CMP-0009226-3: CAP, CERM, 10 uF, 50 V, +/- 10%, X7R, 1210; Manufacturer: MuRata; TaMin_C: -55°C; Polarized: N; SizeAreaWB_mm2: 14.7; Value1: Unknown; U/M: EA; Value: 10uF; TaMax_C: 125°C; SizeZ_mm: 2.7; SizeX_mm: 3.2; SizeY_mm: 2.5; Cap_Case: 1210; SizeArea_mm2: 8; Cap_F: 10µF; AEC Category: Q200
C35 C36 = CMP-0009221-2: CAP, CERM, 47 uF, 10 V, +/- 20%, X7R, 1210; Manufacturer: MuRata; TaMin_C: -55°C; Polarized: N; SizeAreaWB_mm2: 14.7; Value1: Unknown; U/M: EA; Value: 47uF; TaMax_C: 125°C; SizeZ_mm: 2.7; SizeX_mm: 3.2; SizeY_mm: 2.5; Cap_Case: 1210; SizeArea_mm2: 8; Cap_F: 47µF; AEC Category: Q200
C37 C41 = CMP-0086437-1: Cap Aluminum Polymer 470uF 16VDC 20% (10 X 10mm) SMD 0.018 Ohm 2600mA 5000h 105C Automotive T/R; Manufacturer: United Chemi-Con; AEC Qualified: Yes; SizeZ_mm: 10.3mm; IRMS_A: 2.6A; Symbol Name: SYM-HHXB160ARA471MJA0G; AEC Grade: Grade 2
C38 C39 = CMP-0009189-2: CAP, CERM, 10 uF, 10 V, +/- 20%, X7R, 1210; Manufacturer: MuRata; TaMin_C: -55°C; Polarized: N; SizeAreaWB_mm2: 14.7; Value1: Unknown; U/M: EA; Value: 10uF; TaMax_C: 125°C; SizeZ_mm: 2.2; SizeX_mm: 3.2; SizeY_mm: 2.5; Cap_Case: 1210; SizeArea_mm2: 8; Cap_F: 10µF; AEC Category: Q200
C40 C42 = CMP-0008253-2: CAP, CERM, 2200 pF, 250 V, +/- 10%, X7R, 0805; Manufacturer: MuRata; TaMin_C: -55°C; Polarized: N; SizeAreaWB_mm2: 6.75; Value1: Unknown; U/M: EA; Value: 2200pF; TaMax_C: 125°C; SizeZ_mm: 1.45; SizeX_mm: 2; SizeY_mm: 1.25; Cap_Case: 0805; Value2: 250V; SizeArea_mm2: 2.5; AEC Category: Q200
C43 = CMP-0007373-4: CAP, CERM, 0.47 uF, 10 V, +/- 10%, X7R, 0603; Manufacturer: MuRata; TaMin_C: -55°C; Polarized: N; SizeAreaWB_mm2: 4.68; Value1: Unknown; U/M: EA; Value: 0.47uF; TaMax_C: 125°C; SizeZ_mm: 1; SizeX_mm: 1.6; SizeY_mm: 0.8; SizeArea_mm2: 1.28; AEC Category: Q200
C44-C46 = CMP-0007499-4: CAP, CERM, 2.2 uF, 16 V, +/- 10%, X7R, 0603; Manufacturer: MuRata; TaMin_C: -55°C; Polarized: N; SizeAreaWB_mm2: 4.68; Value1: Unknown; U/M: EA; Value: 2.2uF; TaMax_C: 125°C; SizeZ_mm: 1; SizeX_mm: 1.6; SizeY_mm: 0.8; SizeArea_mm2: 1.28; AEC Category: Q200
C47 C48 = CMP-0006641-2: CAP, CERM, 0.1 uF, 16 V, +/- 10%, X7R, 0402; Manufacturer: MuRata; TaMin_C: -55°C; Polarized: N; SizeAreaWB_mm2: 3; Value1: Unknown; U/M: EA; Value: 0.1uF; TaMax_C: 125°C; SizeZ_mm: 0.6; SizeX_mm: 1; SizeY_mm: 0.5; Cap_F: 100nF; AEC Category: Q200
C49 C50 = CMP-0006704-2: CAP, CERM, 2200 pF, 100 V, +/- 10%, X7R, 0402; Manufacturer: MuRata; TaMin_C: -55°C; Polarized: N; SizeAreaWB_mm2: 3; Value1: Unknown; U/M: EA; Value: 2200pF; TaMax_C: 125°C; SizeZ_mm: 0.6; SizeX_mm: 1; SizeY_mm: 0.5; Value2: 100V; Cap_F: 2.2nF; AEC Category: Q200
C51 = CMP-0006454-2: CAP, CERM, 33 pF, 50 V, +/- 5%, C0G/NP0, 0402; Manufacturer: MuRata; TaMin_C: -55°C; Polarized: N; SizeAreaWB_mm2: 3; Value1: Unknown; U/M: EA; Value: 33pF; TaMax_C: 125°C; SizeZ_mm: 0.6; SizeX_mm: 1; SizeY_mm: 0.5; Value2: 50V; AEC Category: Q200
C52 = CMP-0006632-2: CAP, CERM, 0.033 uF, 10 V, +/- 10%, X7R, 0402; Manufacturer: MuRata; TaMin_C: -55°C; Polarized: N; SizeAreaWB_mm2: 3; Value1: Unknown; U/M: EA; TaMax_C: 125°C; SizeZ_mm: 0.6; SizeX_mm: 1; SizeY_mm: 0.5; Value2: 10V; Cap_F: 33nF; AEC Category: Q200
C53 = CMP-0006636-2: CAP, CERM, 0.068 uF, 10 V, +/- 10%, X7R, 0402; Manufacturer: MuRata; TaMin_C: -55°C; Polarized: N; SizeAreaWB_mm2: 3; Value1: Unknown; U/M: EA; TaMax_C: 125°C; SizeZ_mm: 0.6; SizeX_mm: 1; SizeY_mm: 0.5; Value2: 10V; Cap_F: 68nF; AEC Category: Q200
C54 = CMP-0007371-4: CAP, CERM, 0.33 uF, 10 V, +/- 10%, X7R, 0603; Manufacturer: MuRata; TaMin_C: -55°C; Polarized: N; SizeAreaWB_mm2: 4.68; Value1: Unknown; U/M: EA; TaMax_C: 125°C; SizeZ_mm: 1; SizeX_mm: 1.6; SizeY_mm: 0.8; Value2: 10V; SizeArea_mm2: 1.28; Value: 0.33uF; AEC Category: Q200
C55 = CMP-0006421-2: CAP, CERM, 150 pF, 50 V, +/- 5%, C0G/NP0, 0402; Manufacturer: MuRata; TaMin_C: -55°C; Polarized: N; SizeAreaWB_mm2: 3; Value1: Unknown; U/M: EA; Value: 150pF; TaMax_C: 125°C; SizeZ_mm: 0.6; SizeX_mm: 1; SizeY_mm: 0.5; Value2: 50V; AEC Category: Q200
C56 = CMP-0006647-2: CAP, CERM, 0.022 uF, 16 V, +/- 10%, X7R, 0402; Manufacturer: MuRata; TaMin_C: -55°C; Polarized: N; SizeAreaWB_mm2: 3; Value1: Unknown; U/M: EA; TaMax_C: 125°C; SizeZ_mm: 0.6; SizeX_mm: 1; SizeY_mm: 0.5; Value2: 16V; Cap_F: 22nF; AEC Category: Q200
C57 = CMP-0006650-2: CAP, CERM, 0.033 uF, 16 V, +/- 10%, X7R, 0402; Manufacturer: MuRata; TaMin_C: -55°C; Polarized: N; SizeAreaWB_mm2: 3; Value1: Unknown; U/M: EA; TaMax_C: 125°C; SizeZ_mm: 0.6; SizeX_mm: 1; SizeY_mm: 0.5; Value2: 16V; Cap_F: 33nF; AEC Category: Q200
C58 = CMP-0006639-2: CAP, CERM, 0.01 uF, 16 V, +/- 10%, X7R, 0402; Manufacturer: MuRata; TaMin_C: -55°C; Polarized: N; SizeAreaWB_mm2: 3; Value1: Unknown; U/M: EA; Value: 0.01uF; TaMax_C: 125°C; SizeZ_mm: 0.6; SizeX_mm: 1; SizeY_mm: 0.5; Cap_F: 10nF; AEC Category: Q200
D2 D3 = CMP-0028377-2: Diode, Schottky, 60 V, 1 A, SOD-123F; Manufacturer: Nexperia; Value1: 1A; Value2: 0.57V; TJmax_C: 150°C; Green_REACh: Incomplete; Vr_V: 60V; SizeY_mm: 1.6; Vf_V: 570mV; SizeArea_mm2: 5.6; AEC Category: Q101; SizeZ_mm: 1.1; SizeX_mm: 3.5; Value: 60V; Green_Lifecycle: Not Set; SizeAreaWB_mm2: 11.7
J9 J10 = CMP-0054828-1: Terminal Block, 5 mm, 2x1, Tin, TH; Manufacturer: Wurth Elektronik; CNHeader: FALSE; Green_Lifecycle: Active; Green_REACh: Passed; CT: TRUE
J11-J14 = CMP-0055086-1: Header, 100mil, 3x1, TH; Manufacturer: Mill-Max; CNHeader: TRUE; Green_Lifecycle: Active; Green_REACh: Passed; CT: FALSE
L5 = CMP-0061019-2: Inductor, Shielded, Composite, 10 µH, 7 A, 0.02982 ohm, AEC-Q200 Grade 1, SMD; Manufacturer: Coilcraft; Irms: 9.2A @ 40C rise; Green_REACh: Incomplete; Imax_A: 7.6A; SizeX_mm: 6.36; Value: 10uH; Ind_H: 10µH; AEC Category: Q200; AEC Qualified: Y; SizeArea_mm2: 41.7216; SizeZ_mm: 6.1; Isat: 7.6A @ 30% inductance drop; Green_Lifecycle: Not Set; AEC Grade: 1; SizeAreaWB_mm2: 71.5616; SizeY_mm: 6.56
L6 = CMP-0060945-1: Inductor, Shielded, Composite, 1.5 uH, 36.6 A, 0.0016 ohm, SMD; Manufacturer: Coilcraft; Isat: 36.6A @ 30% inductance drop; Irms: 40.5A @ 40C rise; Green_Lifecycle: Not Set; SizeAreaWB_mm2: 159.6; DCR_ohm: 1.6m; Green_REACh: Incomplete; Value: 1.5uH; Imax_A: 36.6A; SizeZ_mm: 10; SizeX_mm: 11.3; SizeArea_mm2: 113; Ind_H: 1.5µH; AEC Category: Q200
Q3-Q8 = CMP-0080660-1: MOSFET, N-CH, 40 V, 40 A, AEC-Q101, SON-8; Alternate Manufacturer: None; Manufacturer: Infineon Technologies; PartNumber: IPZ40N04S5L4R8ATMA1; Rdson45_ohm: 6.7m; QgTyp_nC: 22; SizeAreaWB_mm2: 18.49; Vgs_V: 16V; Value1: 0.0067 ohm; VdsMax_V: 40V; Value: 40V; IdsMax_A: 40A; SizeZ_mm: 1.15; SizeX_mm: 3.3; Value2: 22 nC; SizeArea_mm2: 10.89; ChType: N; AEC Qualified: Y; AEC Category: Q101
R12 = CMP-0015211-2: RES, 0.013, 1%, 1 W, 0612; Manufacturer: Susumu Co Ltd; Power_W: 1W; TempCo: 200 ppm/C; SizeAreaWB_mm2: 10.92; Value_Code: R013; U/M: EA; Value: 0.013; EIA_Code: E96; SizeX_mm: 1.6; SizeY_mm: 3.2; SizeZ_mm: 0.85; SizeArea_mm2: 5.12; AEC Category: Q200
R13 R15 = CMP-0016512-2: RES, 0.005, 1%, 1.5 W, 2010; Manufacturer: Stackpole Electronics Inc; Power_W: 1.5W; TempCo: 50 ppm/C; Value_Code: 5L000; U/M: EA; Value: 0.005; EIA_Code: E96; Res_ohm: 5m; SizeX_mm: 5; SizeY_mm: 2.5; SizeZ_mm: 1.66; SizeArea_mm2: 12.5; AEC Category: Q200
R14 = CMP-0020487-2: RES, 1.0, 5%, 0.125 W, 0805; Manufacturer: Vishay-Dale; Power_W: 125mW; TempCo: 200 ppm/C; Value_Code: 1R00; U/M: EA; Value: 1.0; EIA_Code: E24; Res_ohm: 1; SizeX_mm: 2; SizeY_mm: 1.25; SizeZ_mm: 1.45; Value2: 0.125W; SizeArea_mm2: 2.5; VDC_V: 150V; AEC Category: Q200
R16 = CMP-0016745-3: RES, 1.00, 1%, 0.25 W, AEC-Q200 Grade 0, 1206; Manufacturer: Vishay-Dale; Power_W: 250mW; TempCo: 100 ppm/C; Value_Code: 1R00; Value: 1.00; EIA_Code: E96; Res_ohm: 1; SizeX_mm: 3.2; SizeY_mm: 1.6; SizeZ_mm: 1.35; Value2: 0.25W; SizeArea_mm2: 5.12; AEC Qualified: Y; VDC_V: 200V; AEC Category: Q200; AEC Grade: 0
R17 = CMP-0022170-4: RES, 1.00, 1%, 0.1 W, AEC-Q200 Grade 0, 0603; Manufacturer: Vishay-Dale; Power_W: 100mW; TempCo: 100 ppm/C; Value_Code: 1R00; Value: 1.00; EIA_Code: E96; Res_ohm: 1; SizeX_mm: 1.6; SizeY_mm: 0.8; Value2: 0.1W; SizeArea_mm2: 1.28; AEC Qualified: Y; VDC_V: 75V; AEC Category: Q200; AEC Grade: 0
R18 R21 R23-R25 R28-R30 = CMP-0025874-1: RES, 0, 5%, 0.1 W, 0603; Manufacturer: Panasonic; Power_W: 100mW; TempCo: 600 ppm/C; Value_Code: 0000; U/M: EA; Value: 0; EIA_Code: E24; SizeX_mm: 1.6; SizeY_mm: 0.8; SizeZ_mm: 1; Value2: 0.1W; SizeArea_mm2: 1.28; VDC_V: 50V; AEC Category: Q200
R19 R20 = CMP-0022302-4: RES, 2.00, 1%, 0.1 W, AEC-Q200 Grade 0, 0603; Manufacturer: Vishay-Dale; Power_W: 100mW; TempCo: 100 ppm/C; Value_Code: 2R00; Value: 2.00; EIA_Code: E96; Res_ohm: 2; SizeX_mm: 1.6; SizeY_mm: 0.8; SizeZ_mm: 1; Value2: 0.1W; SizeArea_mm2: 1.28; AEC Qualified: Y; VDC_V: 75V; AEC Category: Q200; AEC Grade: 0
R22 = CMP-0022396-4: RES, 3.01, 1%, 0.1 W, AEC-Q200 Grade 0, 0603; Manufacturer: Vishay-Dale; Power_W: 100mW; TempCo: 100 ppm/C; Value_Code: 3R01; Value: 3.01; EIA_Code: E96; SizeX_mm: 1.6; SizeY_mm: 0.8; SizeZ_mm: 1; Value2: 0.1W; SizeArea_mm2: 1.28; AEC Qualified: Y; VDC_V: 75V; AEC Category: Q200; AEC Grade: 0
R26 R27 R31 R32 = CMP-0022448-4: RES, 49.9, 1%, 0.1 W, AEC-Q200 Grade 0, 0603; Manufacturer: Vishay-Dale; Power_W: 100mW; TempCo: 100 ppm/C; Value_Code: 49R9; Value: 49.9; EIA_Code: E96; SizeX_mm: 1.6; SizeY_mm: 0.8; SizeZ_mm: 1; Value2: 0.1W; SizeArea_mm2: 1.28; AEC Qualified: Y; VDC_V: 75V; AEC Category: Q200; AEC Grade: 0
R33 = CMP-0022585-4: RES, 73.2 k, 1%, 0.1 W, AEC-Q200 Grade 0, 0603; Manufacturer: Vishay-Dale; Power_W: 100mW; TempCo: 100 ppm/C; Value_Code: 73k2; Value: 73.2k; EIA_Code: E96; SizeX_mm: 1.6; SizeY_mm: 0.8; SizeZ_mm: 1; Value2: 0.1W; SizeArea_mm2: 1.28; AEC Qualified: Y; VDC_V: 75V; AEC Category: Q200; AEC Grade: 0
R34 = CMP-0022430-4: RES, 45.3 k, 1%, 0.1 W, AEC-Q200 Grade 0, 0603; Manufacturer: Vishay-Dale; Power_W: 100mW; TempCo: 100 ppm/C; Value_Code: 45k3; Value: 45.3k; EIA_Code: E96; SizeX_mm: 1.6; SizeY_mm: 0.8; SizeZ_mm: 1; Value2: 0.1W; SizeArea_mm2: 1.28; AEC Qualified: Y; VDC_V: 75V; AEC Category: Q200; AEC Grade: 0
R35 = CMP-0022066-4: RES, 15.0 k, 1%, 0.1 W, AEC-Q200 Grade 0, 0603; Manufacturer: Vishay-Dale; Power_W: 100mW; TempCo: 100 ppm/C; Value_Code: 15k0; Value: 15.0k; EIA_Code: E96; Res_ohm: 15k; SizeX_mm: 1.6; SizeY_mm: 0.8; SizeZ_mm: 1; Value2: 0.1W; SizeArea_mm2: 1.28; AEC Qualified: Y; VDC_V: 75V; AEC Category: Q200; AEC Grade: 0
R36 = CMP-0022097-4: RES, 18.2 k, 1%, 0.1 W, AEC-Q200 Grade 0, 0603; Manufacturer: Vishay-Dale; Power_W: 100mW; TempCo: 100 ppm/C; Value_Code: 18k2; Value: 18.2k; EIA_Code: E96; SizeX_mm: 1.6; SizeY_mm: 0.8; SizeZ_mm: 1; Value2: 0.1W; SizeArea_mm2: 1.28; AEC Qualified: Y; VDC_V: 75V; AEC Category: Q200; AEC Grade: 0
R37 R38 = CMP-0021998-4: RES, 10.0 k, 1%, 0.1 W, AEC-Q200 Grade 0, 0603; Manufacturer: Vishay-Dale; Power_W: 100mW; TempCo: 100 ppm/C; Value_Code: 10k0; Value: 10.0k; EIA_Code: E96; Res_ohm: 10k; SizeX_mm: 1.6; SizeY_mm: 0.8; SizeZ_mm: 1; Value2: 0.1W; SizeArea_mm2: 1.28; AEC Qualified: Y; VDC_V: 75V; AEC Category: Q200; AEC Grade: 0
R39 = CMP-0022494-4: RES, 54.9 k, 1%, 0.1 W, AEC-Q200 Grade 0, 0603; Manufacturer: Vishay-Dale; Power_W: 100mW; TempCo: 100 ppm/C; Value_Code: 54k9; Value: 54.9k; EIA_Code: E96; SizeX_mm: 1.6; SizeY_mm: 0.8; SizeZ_mm: 1; Value2: 0.1W; SizeArea_mm2: 1.28; AEC Qualified: Y; VDC_V: 75V; AEC Category: Q200; AEC Grade: 0
TP15 TP17 TP19 TP20 = CMP-0055147-1: Test Point, Multipurpose, Red, TH; Manufacturer: Keystone; CNHeader: FALSE; Green_Lifecycle: Active; Green_REACh: Passed; ContactFinish: Silver; CT: TRUE
TP16 TP18 TP25 TP26 = CMP-0055148-1: Test Point, Multipurpose, Black, TH; Manufacturer: Keystone; CNHeader: FALSE; Green_Lifecycle: Active; Green_REACh: Passed; ContactFinish: Silver; CT: TRUE
TP21 TP22 = CMP-0055149-1: Test Point, Multipurpose, White, TH; Manufacturer: Keystone; CNHeader: FALSE; Green_Lifecycle: Active; Green_REACh: Passed; ContactFinish: Silver; CT: TRUE
TP23 TP24 = CMP-0055151-1: Test Point, Multipurpose, Yellow, TH; Manufacturer: Keystone; CNHeader: FALSE; Green_Lifecycle: Active; Green_REACh: Passed; ContactFinish: Silver; CT: TRUE
U4 = CMP-0079128-2: 3.5-V to 65-V Low IQ, Dual Synchronous Buck DC-DC Controller, RWG0040A (VQFNP-40); Alternate Manufacturer: Texas Instruments; Alternate PartNumber: LM5143QRWGTQ1; SizeX_mm: 6; AEC Category: Q200; SizeArea_mm2: 36; CompType: IC; Rating: Automotive; SizeZ_mm: 0.9; AEC Qualified: Y; SizeAreaWB_mm2: 64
